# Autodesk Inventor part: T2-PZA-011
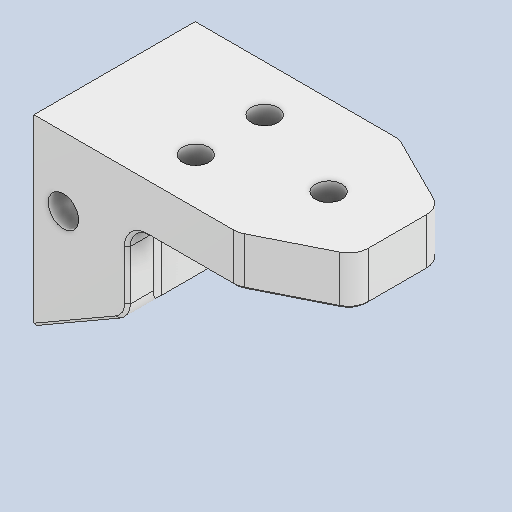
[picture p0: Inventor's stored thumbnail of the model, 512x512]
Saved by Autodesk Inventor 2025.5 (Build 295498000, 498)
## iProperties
Created: 2026-10
Part Number: T2-PZA-011
Material: Genérico
Description: Punta flexible removible
Document SubType Name: Modeling
Designer: Luis MuÃ±oz
Density: 1 g/cm^3
Appearance: Valor por defecto
Project: TESIS 2 - Plataforma mecatrÃ³nica preventiva desacoplada
Sending System: ONSHAPE BY PTC INC, 1.194
Preprocessor: ST-DEVELOPER v20
Material_Fabricacion: TPU
Title: Punta flexible removible
Revision Number: 00
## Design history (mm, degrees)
feature "Removable_Tip"
node "Sólido1"
